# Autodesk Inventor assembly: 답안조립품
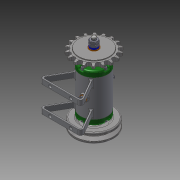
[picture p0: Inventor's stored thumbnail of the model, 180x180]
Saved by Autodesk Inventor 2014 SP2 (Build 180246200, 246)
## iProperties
Created: 2016-03
Part Number: 답안조립품
Document SubType Name: Assembly
Designer: 이도윤
Author: 이도윤
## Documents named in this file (16)
- C:\Users\201-13\Desktop\460307V1016\답안조립품.iam
- C:\Users\201-13\Desktop\460307V1016\본체.ipt
- C:\Users\201-13\Desktop\460307V1016\커버.ipt
- C:\Users\201-13\Desktop\460307V1016\축.ipt
- C:\Users\201-13\Desktop\460307V1016\키 3 x 3 x 12.ipt
- C:\Users\201-13\Desktop\460307V1016\베어링 15 x 32 x 9.ipt
- C:\Users\201-13\Desktop\460307V1016\V벨트풀리.ipt
- C:\Users\201-13\Desktop\460307V1016\스프링와셔 8.ipt
- C:\Users\201-13\Desktop\460307V1016\와셔 8x17.ipt
- C:\Users\201-13\Desktop\460307V1016\너트 M 8.ipt
- C:\Users\201-13\Desktop\460307V1016\스프로킷.ipt
- C:\Users\201-13\Desktop\460307V1016\오일 실 15 25 7.ipt
- C:\Users\201-13\Desktop\460307V1016\볼트 M4 x 12.ipt
- C:\Users\201-13\Desktop\460307V1016\니플 M 6 x 0.75.ipt
- C:\Users\201-13\Desktop\460307V1016\볼트 M 6 x 8.ipt
- C:\Users\201-13\Desktop\460307V1016\와셔 6x11.5.ipt
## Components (11 placed, 3 different names)
1. KS B 2023 6002 - 15 x 32 x 9:1
2. KS B 2023 6002 - 15 x 32 x 9:2
3. V벨트풀리:1
4. ISO 4762 M4 x 12:2
5. ISO 4762 M4 x 12:3
6. ISO 4762 M4 x 12:4
7. ISO 4762 M4 x 12:5
8. ISO 4762 M4 x 12:1
9. ISO 4762 M4 x 12:6
10. ISO 4762 M4 x 12:7
11. ISO 4762 M4 x 12:8
